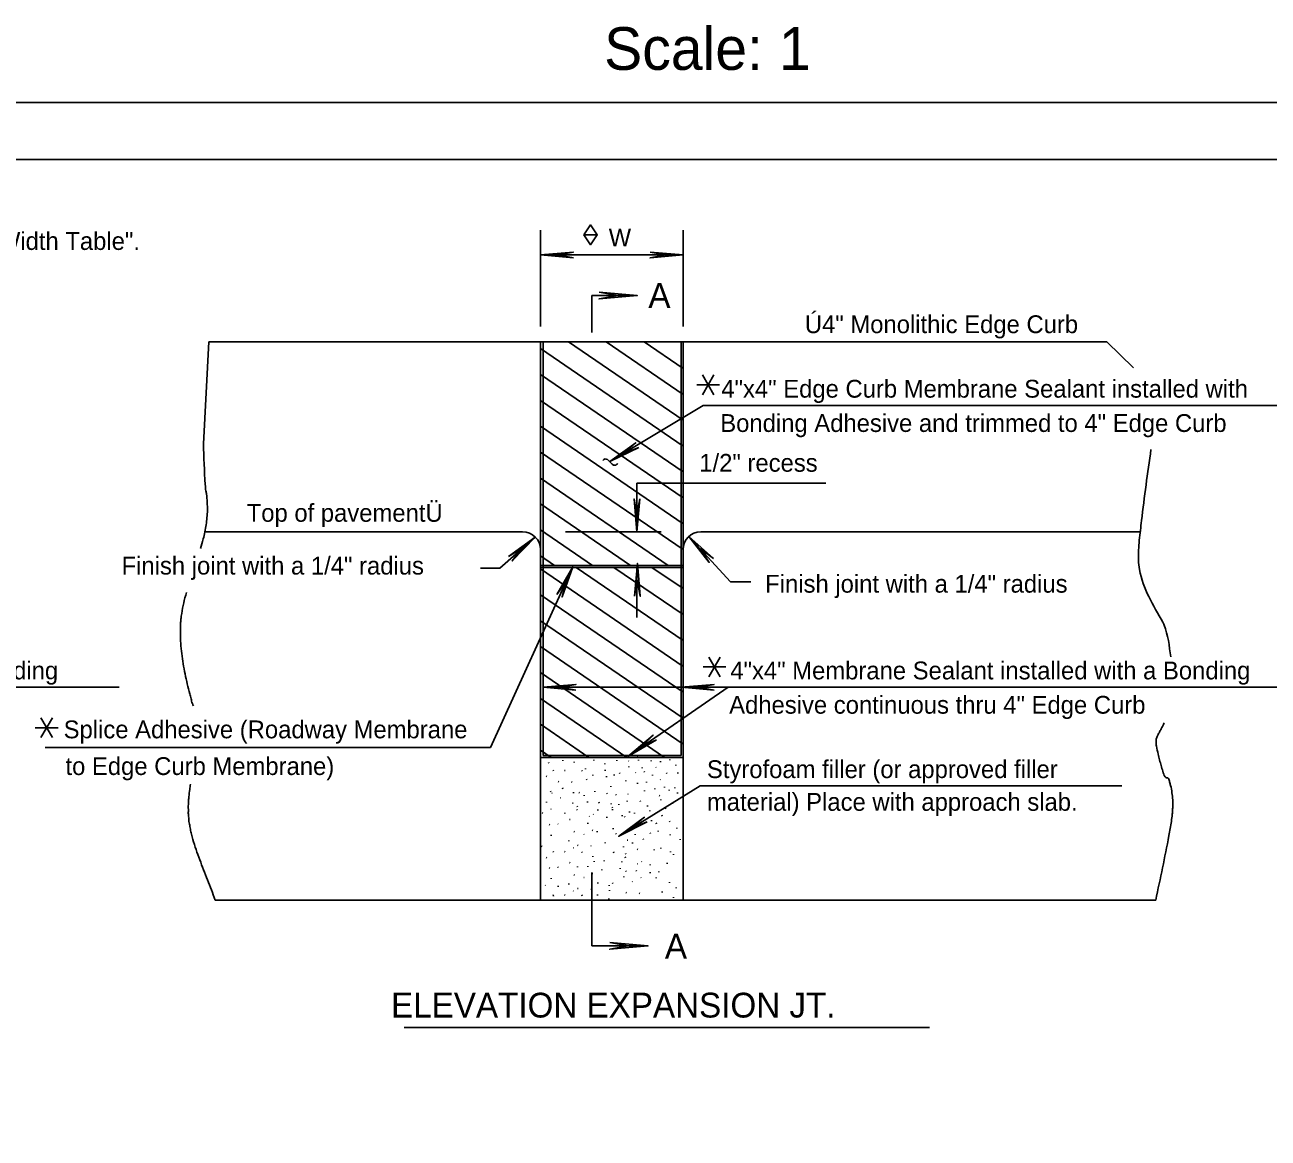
# Model space of a CAD drawing. Extents: x 1000 to 1036, y 1000 to 1022.7.
# Drawn here: x 1012.07 to 1022.98, y 1012.91 to 1022.68 of the extents above; entities that cross this region are included whole.
import ezdxf

# ---------------------------------------------------------------- set-up
doc = ezdxf.new("R2010")
doc.units = 0
for name, color, linetype in [('KS_Border Text_Z_N', 7, 'Continuous'), ('KS_Borders_Z_N', 7, 'Continuous'), ('KS_PlotShape_z_e', 7, 'Continuous'), ('rd_Detail Annotation_z_n', 7, 'Continuous'), ('rd_Details_z_n', 7, 'Continuous'), ('rd_Dimensions_z_n', 7, 'Continuous'), ('rd_Misc Label_z_n', 7, 'Continuous'), ('rd_Symbols_z_n', 7, 'Continuous')]:
    doc.layers.add(name, color=color, linetype=linetype)

msp = doc.modelspace()

# ---------------------------------------------------------------- linework, layer by layer
at = {"layer": 'KS_Borders_Z_N'}
for points in [[(999.998, 1021.998), (1035.998, 1021.998), (1035.998, 999.998), (999.998, 999.998)], [(1001.998, 1000.498), (1035.498, 1000.498), (1035.498, 1021.498), (1001.998, 1021.498)]]:
    msp.add_lwpolyline(points, close=True, dxfattribs=at)
at = {"layer": 'KS_PlotShape_z_e'}
msp.add_lwpolyline([(999.998, 999.998), (1035.998, 999.998), (1035.998, 1021.998), (999.998, 1021.998)], close=True, dxfattribs=at)
at = {"layer": 'rd_Detail Annotation_z_n'}
for p, q in [((1018.024, 1019.338), (1017.207, 1018.846)), ((1018.024, 1019.338), (1023.189, 1019.338)), ((1016.24, 1017.91), (1016.551, 1018.184)), ((1018.266, 1017.791), (1017.898, 1018.189)), ((1016.88, 1017.924), (1016.16, 1016.337)), ((1005.801, 1016.866), (1012.902, 1016.866)), ((1016.62, 1016.866), (1023.268, 1016.866)), ((1016.16, 1016.337), (1012.251, 1016.337)), ((1017.284, 1015.558), (1017.998, 1016)), ((1017.998, 1016), (1021.698, 1016)), ((1015.402, 1013.88), (1020.012, 1013.88))]:
    msp.add_line(p, q, dxfattribs=at)
at = {"layer": 'rd_Details_z_n'}
for p, q in [((1017.049, 1020.302), (1017.447, 1020.302)), ((1017.049, 1019.978), (1017.049, 1020.302)), ((1013.688, 1019.897), (1013.641, 1019.003)), ((1016.598, 1019.897), (1013.688, 1019.897)), ((1016.598, 1019.897), (1016.598, 1014.999)), ((1017.848, 1019.897), (1016.598, 1019.897)), ((1017.848, 1018.982), (1016.598, 1019.837)), ((1016.62, 1019.889), (1016.62, 1016.266)), ((1017.848, 1019.209), (1016.842, 1019.897)), ((1017.848, 1019.436), (1017.174, 1019.897)), ((1017.848, 1019.664), (1017.507, 1019.897)), ((1017.831, 1019.897), (1017.831, 1016.266)), ((1017.848, 1019.897), (1017.848, 1014.999)), ((1017.848, 1019.897), (1021.568, 1019.897)), ((1021.568, 1019.897), (1021.801, 1019.668)), ((1017.848, 1018.755), (1016.598, 1019.61)), ((1017.848, 1018.528), (1016.598, 1019.383)), ((1017.848, 1018.301), (1016.598, 1019.156)), ((1017.848, 1018.074), (1016.598, 1018.928)), ((1017.719, 1017.935), (1016.598, 1018.701)), ((1017.386, 1017.935), (1016.598, 1018.474)), ((1016.441, 1018.23), (1013.654, 1018.23)), ((1017.054, 1017.935), (1016.598, 1018.247)), ((1018.004, 1018.23), (1021.859, 1018.23)), ((1016.722, 1017.935), (1016.598, 1018.02)), ((1016.598, 1017.935), (1017.848, 1017.935)), ((1016.598, 1017.918), (1017.848, 1017.918)), ((1017.848, 1017.049), (1016.598, 1017.904)), ((1017.848, 1017.277), (1016.91, 1017.918)), ((1017.848, 1017.504), (1017.242, 1017.918)), ((1017.848, 1017.731), (1017.574, 1017.918)), ((1017.848, 1016.822), (1016.598, 1017.677)), ((1017.848, 1016.595), (1016.598, 1017.45)), ((1017.848, 1016.368), (1016.598, 1017.223)), ((1017.687, 1016.251), (1016.598, 1016.996)), ((1017.354, 1016.251), (1016.598, 1016.768)), ((1017.022, 1016.251), (1016.598, 1016.541)), ((1016.69, 1016.251), (1016.598, 1016.314)), ((1016.598, 1016.251), (1017.848, 1016.251)), ((1016.62, 1016.266), (1017.831, 1016.266)), ((1016.67, 1016.199), (1016.669, 1016.205)), ((1016.795, 1016.219), (1016.794, 1016.226)), ((1016.894, 1016.205), (1016.893, 1016.211)), ((1017.066, 1016.222), (1017.065, 1016.229)), ((1017.266, 1016.219), (1017.266, 1016.226)), ((1017.369, 1016.22), (1017.374, 1016.218)), ((1017.444, 1016.254), (1017.449, 1016.252)), ((1017.459, 1016.222), (1017.458, 1016.229)), ((1017.569, 1016.216), (1017.568, 1016.222)), ((1017.651, 1016.21), (1017.65, 1016.217)), ((1017.732, 1016.225), (1017.731, 1016.232)), ((1016.711, 1016.132), (1016.71, 1016.139)), ((1016.808, 1016.137), (1016.813, 1016.135)), ((1016.962, 1016.129), (1016.961, 1016.136)), ((1016.993, 1016.146), (1016.992, 1016.153)), ((1017.057, 1016.091), (1017.056, 1016.098)), ((1017.162, 1016.19), (1017.161, 1016.197)), ((1017.166, 1016.134), (1017.166, 1016.141)), ((1017.245, 1016.093), (1017.245, 1016.1)), ((1017.293, 1016.109), (1017.292, 1016.116)), ((1017.374, 1016.164), (1017.374, 1016.17)), ((1017.431, 1016.118), (1017.435, 1016.116)), ((1017.491, 1016.155), (1017.49, 1016.162)), ((1017.506, 1016.126), (1017.51, 1016.121)), ((1017.581, 1016.091), (1017.58, 1016.098)), ((1017.61, 1016.165), (1017.614, 1016.162)), ((1017.705, 1016.108), (1017.704, 1016.115)), ((1017.785, 1016.178), (1017.784, 1016.185)), ((1017.803, 1016.11), (1017.802, 1016.117)), ((1016.647, 1016.086), (1016.652, 1016.084)), ((1016.753, 1016.04), (1016.758, 1016.037)), ((1016.87, 1016.036), (1016.875, 1016.033)), ((1017.003, 1016.053), (1017.002, 1016.059)), ((1017.177, 1016.078), (1017.176, 1016.085)), ((1017.216, 1015.991), (1017.216, 1015.998)), ((1017.347, 1016.041), (1017.346, 1016.048)), ((1017.449, 1016.02), (1017.448, 1016.027)), ((1017.528, 1016.03), (1017.528, 1016.037)), ((1017.647, 1016.056), (1017.652, 1016.054)), ((1017.686, 1015.986), (1017.685, 1015.993)), ((1017.775, 1015.98), (1017.775, 1015.986)), ((1016.687, 1015.947), (1016.686, 1015.954)), ((1016.696, 1015.937), (1016.699, 1015.936)), ((1016.772, 1015.897), (1016.777, 1015.895)), ((1016.793, 1015.975), (1016.792, 1015.982)), ((1016.888, 1015.937), (1016.888, 1015.944)), ((1016.934, 1015.942), (1016.939, 1015.939)), ((1016.981, 1015.912), (1016.98, 1015.919)), ((1017.075, 1015.947), (1017.074, 1015.954)), ((1017.182, 1015.93), (1017.181, 1015.937)), ((1017.261, 1015.919), (1017.26, 1015.926)), ((1017.363, 1015.929), (1017.368, 1015.927)), ((1017.51, 1015.953), (1017.509, 1015.96)), ((1017.602, 1015.972), (1017.602, 1015.979)), ((1017.64, 1015.915), (1017.645, 1015.913)), ((1017.653, 1015.874), (1017.653, 1015.88)), ((1017.728, 1015.96), (1017.727, 1015.966)), ((1017.8, 1015.935), (1017.8, 1015.942)), ((1016.65, 1015.854), (1016.649, 1015.861)), ((1016.687, 1015.797), (1016.692, 1015.795)), ((1016.812, 1015.758), (1016.811, 1015.765)), ((1016.878, 1015.85), (1016.883, 1015.848)), ((1016.918, 1015.787), (1016.917, 1015.793)), ((1016.918, 1015.823), (1016.922, 1015.818)), ((1017.011, 1015.856), (1017.01, 1015.863)), ((1017.102, 1015.786), (1017.101, 1015.793)), ((1017.111, 1015.85), (1017.11, 1015.857)), ((1017.219, 1015.839), (1017.218, 1015.845)), ((1017.228, 1015.808), (1017.227, 1015.815)), ((1017.229, 1015.788), (1017.229, 1015.795)), ((1017.285, 1015.833), (1017.284, 1015.84)), ((1017.358, 1015.863), (1017.357, 1015.87)), ((1017.379, 1015.768), (1017.379, 1015.775)), ((1017.474, 1015.863), (1017.473, 1015.87)), ((1017.537, 1015.821), (1017.537, 1015.828)), ((1017.558, 1015.779), (1017.558, 1015.785)), ((1017.696, 1015.8), (1017.695, 1015.806)), ((1017.757, 1015.843), (1017.756, 1015.85)), ((1016.613, 1015.763), (1016.617, 1015.761)), ((1016.674, 1015.661), (1016.679, 1015.659)), ((1016.749, 1015.669), (1016.753, 1015.664)), ((1016.853, 1015.707), (1016.858, 1015.705)), ((1017.014, 1015.669), (1017.013, 1015.676)), ((1017.024, 1015.734), (1017.028, 1015.732)), ((1017.059, 1015.753), (1017.064, 1015.75)), ((1017.181, 1015.721), (1017.18, 1015.728)), ((1017.315, 1015.736), (1017.314, 1015.743)), ((1017.337, 1015.726), (1017.336, 1015.733)), ((1017.421, 1015.758), (1017.421, 1015.764)), ((1017.482, 1015.675), (1017.481, 1015.682)), ((1017.571, 1015.692), (1017.571, 1015.699)), ((1017.615, 1015.668), (1017.614, 1015.675)), ((1017.664, 1015.736), (1017.663, 1015.743)), ((1017.731, 1015.684), (1017.73, 1015.691)), ((1016.692, 1015.563), (1016.692, 1015.57)), ((1016.891, 1015.599), (1016.895, 1015.596)), ((1016.977, 1015.578), (1016.982, 1015.575)), ((1017.052, 1015.612), (1017.057, 1015.61)), ((1017.095, 1015.595), (1017.094, 1015.602)), ((1017.236, 1015.622), (1017.235, 1015.629)), ((1017.261, 1015.578), (1017.26, 1015.584)), ((1017.415, 1015.63), (1017.414, 1015.637)), ((1017.429, 1015.571), (1017.429, 1015.578)), ((1017.562, 1015.583), (1017.561, 1015.589)), ((1017.631, 1015.599), (1017.63, 1015.605)), ((1017.736, 1015.568), (1017.735, 1015.575)), ((1017.794, 1015.626), (1017.793, 1015.633)), ((1016.606, 1015.473), (1016.611, 1015.47)), ((1016.845, 1015.515), (1016.845, 1015.522)), ((1016.883, 1015.458), (1016.888, 1015.456)), ((1016.922, 1015.48), (1016.927, 1015.478)), ((1017.039, 1015.476), (1017.043, 1015.474)), ((1017.165, 1015.497), (1017.164, 1015.504)), ((1017.326, 1015.462), (1017.325, 1015.468)), ((1017.359, 1015.525), (1017.364, 1015.523)), ((1017.405, 1015.496), (1017.405, 1015.503)), ((1017.447, 1015.445), (1017.451, 1015.443)), ((1017.5, 1015.53), (1017.499, 1015.537)), ((1017.595, 1015.436), (1017.594, 1015.443)), ((1017.654, 1015.45), (1017.654, 1015.456)), ((1017.824, 1015.526), (1017.823, 1015.533)), ((1016.647, 1015.373), (1016.652, 1015.37)), ((1016.711, 1015.419), (1016.71, 1015.426)), ((1016.808, 1015.424), (1016.813, 1015.421)), ((1016.853, 1015.328), (1016.858, 1015.326)), ((1016.962, 1015.416), (1016.961, 1015.423)), ((1017.057, 1015.378), (1017.056, 1015.385)), ((1017.069, 1015.333), (1017.068, 1015.339)), ((1017.156, 1015.339), (1017.155, 1015.346)), ((1017.24, 1015.414), (1017.239, 1015.421)), ((1017.312, 1015.331), (1017.312, 1015.338)), ((1017.343, 1015.37), (1017.342, 1015.377)), ((1017.343, 1015.406), (1017.347, 1015.401)), ((1017.484, 1015.336), (1017.488, 1015.334)), ((1017.739, 1015.419), (1017.738, 1015.426)), ((1017.765, 1015.396), (1017.764, 1015.402)), ((1016.674, 1015.282), (1016.679, 1015.28)), ((1016.749, 1015.29), (1016.753, 1015.285)), ((1016.891, 1015.22), (1016.895, 1015.217)), ((1016.923, 1015.286), (1016.922, 1015.293)), ((1017.014, 1015.29), (1017.013, 1015.297)), ((1017.049, 1014.596), (1017.049, 1015.24)), ((1017.052, 1015.233), (1017.057, 1015.231)), ((1017.136, 1015.26), (1017.135, 1015.267)), ((1017.298, 1015.273), (1017.297, 1015.28)), ((1017.348, 1015.249), (1017.347, 1015.256)), ((1017.439, 1015.253), (1017.438, 1015.259)), ((1017.449, 1015.318), (1017.453, 1015.316)), ((1017.56, 1015.236), (1017.559, 1015.243)), ((1017.561, 1015.305), (1017.56, 1015.311)), ((1017.637, 1015.243), (1017.637, 1015.249)), ((1017.71, 1015.318), (1017.709, 1015.325)), ((1016.64, 1015.128), (1016.643, 1015.127)), ((1016.692, 1015.184), (1016.692, 1015.191)), ((1016.753, 1015.116), (1016.753, 1015.123)), ((1016.845, 1015.136), (1016.845, 1015.143)), ((1016.977, 1015.198), (1016.982, 1015.196)), ((1017.1, 1015.145), (1017.1, 1015.152)), ((1017.2, 1015.123), (1017.2, 1015.13)), ((1017.231, 1015.144), (1017.23, 1015.151)), ((1017.328, 1015.199), (1017.328, 1015.206)), ((1017.402, 1015.161), (1017.406, 1015.159)), ((1017.477, 1015.196), (1017.481, 1015.194)), ((1017.612, 1015.191), (1017.612, 1015.198)), ((1017.73, 1015.15), (1017.729, 1015.157)), ((1016.712, 1015.032), (1016.71, 1015.046)), ((1016.808, 1015.044), (1016.813, 1015.042)), ((1016.883, 1015.079), (1016.888, 1015.077)), ((1016.922, 1015.101), (1016.927, 1015.099)), ((1016.962, 1015.037), (1016.961, 1015.044)), ((1017.039, 1015.097), (1017.043, 1015.095)), ((1017.098, 1015.04), (1017.097, 1015.047)), ((1017.198, 1015.004), (1017.197, 1015.011)), ((1017.203, 1015.08), (1017.202, 1015.086)), ((1017.347, 1015.064), (1017.352, 1015.061)), ((1017.464, 1015.06), (1017.468, 1015.057)), ((1017.665, 1015.066), (1017.664, 1015.073)), ((1017.765, 1015.018), (1017.764, 1015.024)), ((1017.788, 1015.103), (1017.788, 1015.11)), ((1013.742, 1014.999), (1021.996, 1014.999)), ((1013.742, 1014.999), (1021.597, 1014.999)), ((1017.049, 1014.596), (1017.541, 1014.596))]:
    msp.add_line(p, q, dxfattribs=at)
for centre, start, end in [((1016.441, 1018.074), 0, 90), ((1018.004, 1018.074), 90, 180)]:
    msp.add_arc(centre, 0.156, start, end, dxfattribs=at)
for points in [[(1013.641, 1019.003), (1013.656, 1018.645), (1013.662, 1018.588), (1013.667, 1018.56), (1013.67, 1018.531), (1013.675, 1018.418), (1013.664, 1018.292), (1013.639, 1018.167), (1013.614, 1018.084)], [(1021.954, 1018.953), (1021.871, 1018.328), (1021.861, 1018.242), (1021.851, 1018.156), (1021.845, 1018.069), (1021.844, 1018.026), (1021.844, 1018.005), (1021.844, 1017.983), (1021.853, 1017.898), (1022.059, 1017.437)], [(1017.145, 1018.857), (1017.164, 1018.869), (1017.205, 1018.844), (1017.251, 1018.814), (1017.277, 1018.829)], [(1013.492, 1017.697), (1013.485, 1017.674), (1013.446, 1017.489), (1013.442, 1017.458), (1013.44, 1017.427), (1013.441, 1017.251), (1013.463, 1017.072), (1013.499, 1016.895), (1013.521, 1016.808), (1013.532, 1016.765), (1013.543, 1016.723), (1013.552, 1016.703)], [(1022.059, 1017.437), (1022.069, 1017.412), (1022.127, 1017.133)], [(1022.069, 1016.553), (1022.057, 1016.527), (1022.043, 1016.5), (1022.028, 1016.473), (1022.014, 1016.446), (1022.008, 1016.433), (1022.003, 1016.419), (1021.999, 1016.401), (1021.998, 1016.384), (1022.002, 1016.349), (1022.018, 1016.279), (1022.03, 1016.228), (1022.043, 1016.179), (1022.058, 1016.129), (1022.078, 1016.08), (1022.084, 1016.074), (1022.095, 1016.071), (1022.105, 1016.068), (1022.107, 1016.066), (1022.117, 1016.035), (1022.126, 1016.004), (1022.138, 1015.941), (1022.145, 1015.815), (1022.143, 1015.783), (1022.141, 1015.752), (1022.133, 1015.689), (1022.111, 1015.564), (1021.996, 1014.999)], [(1013.526, 1016.015), (1013.52, 1015.97), (1013.513, 1015.905), (1013.51, 1015.872), (1013.508, 1015.84), (1013.508, 1015.776), (1013.509, 1015.744), (1013.511, 1015.728), (1013.511, 1015.72), (1013.512, 1015.716), (1013.512, 1015.712), (1013.518, 1015.666), (1013.526, 1015.621), (1013.536, 1015.576), (1013.548, 1015.531), (1013.576, 1015.442), (1013.608, 1015.353), (1013.677, 1015.176), (1013.711, 1015.088), (1013.742, 1014.999)]]:
    msp.add_spline(points, degree=3, dxfattribs=at)
at = {"layer": 'rd_Dimensions_z_n'}
for p, q in [((1016.598, 1020.03), (1016.598, 1020.876)), ((1017.848, 1020.03), (1017.848, 1020.876)), ((1016.598, 1020.659), (1017.848, 1020.659)), ((1017.444, 1018.23), (1017.444, 1018.658)), ((1017.444, 1018.658), (1019.1, 1018.658)), ((1016.817, 1018.23), (1017.657, 1018.23)), ((1016.071, 1017.91), (1016.24, 1017.91)), ((1017.444, 1017.478), (1017.444, 1017.918)), ((1018.266, 1017.791), (1018.444, 1017.791)), ((1017.365, 1016.258), (1018.245, 1016.866))]:
    msp.add_line(p, q, dxfattribs=at)
at = {"layer": 'rd_Misc Label_z_n'}
for points in [[(1016.887, 1020.633), (1016.598, 1020.659), (1016.887, 1020.684), (1016.748, 1020.659), (1016.887, 1020.633)], [(1017.559, 1020.684), (1017.848, 1020.659), (1017.559, 1020.633), (1017.698, 1020.659), (1017.559, 1020.684)], [(1017.111, 1020.332), (1017.447, 1020.302), (1017.111, 1020.273), (1017.273, 1020.302), (1017.111, 1020.332)], [(1017.46, 1018.969), (1017.207, 1018.846), (1017.434, 1019.011), (1017.332, 1018.921), (1017.46, 1018.969)], [(1017.47, 1018.519), (1017.444, 1018.23), (1017.419, 1018.519), (1017.444, 1018.38), (1017.47, 1018.519)], [(1016.316, 1018.014), (1016.551, 1018.184), (1016.35, 1017.975), (1016.438, 1018.086), (1016.316, 1018.014)], [(1018.115, 1017.995), (1017.898, 1018.189), (1018.078, 1017.961), (1018.001, 1018.08), (1018.115, 1017.995)], [(1017.422, 1017.664), (1017.448, 1017.953), (1017.473, 1017.664), (1017.447, 1017.803), (1017.422, 1017.664)], [(1016.742, 1017.68), (1016.88, 1017.924), (1016.787, 1017.659), (1016.82, 1017.792), (1016.742, 1017.68)], [(1016.909, 1016.841), (1016.62, 1016.866), (1016.909, 1016.891), (1016.77, 1016.866), (1016.909, 1016.841)], [(1018.12, 1016.841), (1017.831, 1016.866), (1018.12, 1016.891), (1017.981, 1016.866), (1018.12, 1016.841)], [(1017.616, 1016.405), (1017.365, 1016.258), (1017.586, 1016.447), (1017.488, 1016.345), (1017.616, 1016.405)], [(1017.535, 1015.684), (1017.284, 1015.558), (1017.509, 1015.726), (1017.407, 1015.634), (1017.535, 1015.684)], [(1017.205, 1014.625), (1017.541, 1014.596), (1017.205, 1014.567), (1017.366, 1014.596), (1017.205, 1014.625)]]:
    msp.add_lwpolyline(points, dxfattribs=at)
at = {"layer": 'rd_Symbols_z_n'}
for p, q in [((1018.019, 1019.433), (1018.119, 1019.606)), ((1018.119, 1019.433), (1018.019, 1019.606)), ((1017.969, 1019.519), (1018.169, 1019.519)), ((1018.075, 1016.957), (1018.175, 1017.13)), ((1018.175, 1016.957), (1018.075, 1017.13)), ((1018.025, 1017.044), (1018.225, 1017.044)), ((1012.215, 1016.424), (1012.315, 1016.597)), ((1012.315, 1016.424), (1012.215, 1016.597)), ((1012.165, 1016.511), (1012.365, 1016.511))]:
    msp.add_line(p, q, dxfattribs=at)
msp.add_lwpolyline([(1016.978, 1020.836), (1017.037, 1020.923), (1017.096, 1020.836)], dxfattribs=at)
msp.add_lwpolyline([(1016.978, 1020.836), (1017.096, 1020.836), (1017.037, 1020.749)], close=True, dxfattribs=at)

# ---------------------------------------------------------------- texts
at = {"layer": 'KS_Border Text_Z_N'}
msp.add_text('Scale: 1', height=0.375, dxfattribs=at).set_placement((1017.156, 1022.283))
at = {"layer": 'rd_Detail Annotation_z_n'}
for s, height, p in [('W= Formed Concrete Opening Size - See "Temperature Expansion/Pressure Relief Joint Width Table".', 0.15628, (1003.556, 1020.703)), ('A', 0.218, (1017.544, 1020.195)), ('Ú4" Monolithic Edge Curb', 0.15628, (1018.917, 1019.973)), ('4"x4" Edge Curb Membrane Sealant installed with ', 0.15628, (1018.184, 1019.407)), ('Bonding Adhesive and trimmed to 4" Edge Curb', 0.15628, (1018.175, 1019.106)), ('Top of pavementÜ', 0.15628, (1014.02, 1018.318)), ('Finish joint with a 1/4" radius', 0.15628, (1012.922, 1017.855)), ('Finish joint with a 1/4" radius', 0.15628, (1018.569, 1017.696)), ('4"x4" Membrane Sealant installed with a Bonding', 0.15628, (1007.803, 1016.935)), ('4"x4" Membrane Sealant installed with a Bonding', 0.15628, (1018.263, 1016.935)), ('Adhesive continuous thru 4" Edge Curb', 0.15628, (1018.253, 1016.634)), ('Splice Adhesive (Roadway Membrane', 0.15628, (1012.414, 1016.418)), ('to Edge Curb Membrane)', 0.15628, (1012.43, 1016.096)), ('Styrofoam filler (or approved filler', 0.15628, (1018.058, 1016.069)), ('material) Place with approach slab.', 0.15628, (1018.058, 1015.782)), ('A', 0.218, (1017.689, 1014.485)), ('  ELEVATION EXPANSION JT.', 0.21774, (1015.125, 1013.968))]:
    msp.add_text(s, height=height, dxfattribs=at).set_placement(p)
at = {"layer": 'rd_Dimensions_z_n'}
for s, height, p in [('W', 0.156, (1017.196, 1020.735)), ('1/2" recess', 0.15628, (1017.991, 1018.757))]:
    msp.add_text(s, height=height, dxfattribs=at).set_placement(p)

doc.saveas('drawing.dxf')
